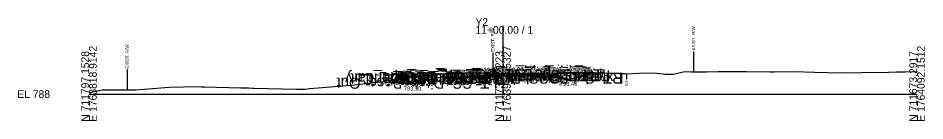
# Model space of a CAD drawing. Extents: x -26 to 1764011, y -10 to 712381.
# Drawn here: x -25.7 to 302.8, y 990.3 to 1027.5 of the extents above; entities that cross this region are included whole.
import ezdxf

# ---------------------------------------------------------------- set-up
doc = ezdxf.new("R2010")
doc.units = 0
for name, color, linetype in [('Default', 7, 'Continuous'), ('Exist Cross Section Cell', 7, 'Continuous'), ('Exist XS Center Line Elevation Label', 7, 'Continuous'), ('Exist XS Ground Line', 7, 'Continuous'), ('Old_Level_10', 7, 'Continuous'), ('Prop CMT Pvmt Course 1', 7, 'Continuous'), ('Prop CMT Pvmt Course 2', 7, 'Continuous'), ('Prop CMT Pvmt Course 3', 7, 'Continuous'), ('Prop CMT Pvmt Surface', 7, 'Continuous'), ('Prop CMT Pvmt Surface Shoulder', 7, 'Continuous'), ('Prop CMT Shld Paved Course 1', 7, 'Continuous'), ('Prop CMT Shld Paved Course 2', 7, 'Continuous'), ('Prop CMT Shld Paved Course 3', 7, 'Continuous'), ('Prop CMT Slope Grass', 7, 'Continuous'), ('Prop CMT Subgrade Earthwork', 7, 'Continuous'), ('Prop XS Ditch Standard Text', 7, 'Continuous'), ('Prop XS Earthwork Shape', 7, 'Continuous'), ('Prop XS SE Text', 7, 'Continuous'), ('Prop XS Side Slope Text', 7, 'Continuous'), ('Scratch_Level_7', 7, 'Continuous')]:
    doc.layers.add(name, color=color, linetype=linetype)

msp = doc.modelspace()

# ---------------------------------------------------------------- linework, layer by layer
at = {"layer": 'Exist Cross Section Cell'}
for p, q in [((150, 1000), (150, 1024.67)), ((0, 1000), (150, 1000)), ((150, 1000), (300, 1000))]:
    msp.add_line(p, q, dxfattribs=at)
at = {"layer": 'Exist XS Ground Line'}
msp.add_lwpolyline([(0, 1000.64), (4.88, 1001.5), (5.22, 1001.5), (14.77, 1001.52), (15.9, 1001.57), (16.96, 1001.58), (29.01, 1002.5), (39.46, 1002.81), (40.65, 1002.69), (41.81, 1002.66), (55, 1002.33), (55.44, 1002.31), (55.92, 1002.31), (57.83, 1002.23), (59.27, 1002.16), (59.86, 1002.12), (75.11, 1001.84), (77.26, 1001.81), (77.72, 1001.77), (78.16, 1001.81), (80.04, 1001.98), (96.3, 1003.37), (100.16, 1003.9), (106.64, 1004.59), (111.93, 1005.57), (116.45, 1006.01), (126.18, 1007.13), (127.43, 1007.28), (128.47, 1007.34), (138.93, 1007.78), (143.38, 1007.62), (150, 1007.48), (150.55, 1007.46), (153.6, 1007.18), (164.39, 1006.19), (170.69, 1007.55), (171.2, 1007.59), (171.75, 1007.6), (172.75, 1007.66), (173.59, 1007.67), (175.49, 1007.69), (177.79, 1007.72), (178.24, 1007.73), (178.61, 1007.73), (180.98, 1007.76), (181.97, 1007.76), (182.55, 1007.76), (182.9, 1007.76), (183.84, 1007.74), (185.22, 1007.7), (186.47, 1007.66), (188.65, 1007.63), (189.22, 1007.62), (189.9, 1007.6), (191.96, 1007.52), (192.33, 1007.5), (194.24, 1007.41), (194.75, 1007.4), (199.16, 1007.6), (204.83, 1007.74), (208.74, 1007.17), (211.75, 1007.25), (215.71, 1008.18), (218.11, 1008.08), (223.7, 1008.11), (227.97, 1008.13), (234.76, 1008.19), (238.11, 1008.21), (246.87, 1008.1), (247.83, 1008.08), (248.22, 1008.09), (255.49, 1008.22), (262.81, 1007.97), (272.66, 1007.65), (279.89, 1007.8), (289.66, 1007.98), (292.54, 1008.02), (293.2, 1008.03), (295.74, 1008.08), (300, 1008.14)], dxfattribs=at)
at = {"layer": 'Old_Level_10'}
for p, q in [((219.01, 1015.49), (219.01, 1008.09)), ((146.29, 1014.96), (146.29, 1007.55)), ((13.78, 1008.92), (13.78, 1001.52)), ((170.69, 1007.55), (170.69, 1005.5)), ((194.75, 1007.4), (194.75, 1005.35))]:
    msp.add_line(p, q, dxfattribs=at)
at = {"layer": 'Prop CMT Pvmt Course 1'}
for points in [[(134.08, 1006.42), (130.39, 1006.27)], [(130.39, 1006.27), (130.39, 1006.02)], [(130.39, 1006.02), (134.08, 1006.17)], [(150, 1007.06), (134.08, 1006.42)], [(134.08, 1006.17), (150, 1006.81)], [(150, 1007.06), (162, 1007.54)], [(162, 1007.29), (150, 1006.81)], [(150, 1006.81), (150, 1007.06)], [(162, 1007.54), (162, 1007.29)]]:
    msp.add_lwpolyline(points, dxfattribs=at)
msp.add_lwpolyline([(150, 1006.81), (150, 1006.81), (150, 1006.81), (150, 1006.81)], close=True, dxfattribs=at)
at = {"layer": 'Prop CMT Pvmt Course 2'}
for points in [[(134.08, 1006.17), (130.39, 1006.02)], [(130.39, 1005.61), (134.08, 1005.75)], [(150, 1006.81), (134.08, 1006.17)], [(134.08, 1005.75), (150, 1006.39)], [(150, 1006.81), (162, 1007.29)], [(162, 1006.87), (150, 1006.39)], [(150, 1006.47), (150, 1006.81)], [(162, 1007.29), (162, 1006.95)]]:
    msp.add_lwpolyline(points, dxfattribs=at)
at = {"layer": 'Prop CMT Pvmt Course 3'}
for points in [[(130.39, 1006.02), (130.39, 1005.61)], [(134.08, 1005.75), (130.39, 1005.61)], [(150, 1006.39), (134.08, 1005.75)], [(150, 1006.39), (162, 1006.87)], [(150, 1006.14), (150, 1006.47)], [(162, 1006.95), (162, 1006.87)]]:
    msp.add_lwpolyline(points, dxfattribs=at)
at = {"layer": 'Prop CMT Pvmt Surface'}
for points in [[(134.08, 1006.42), (130.39, 1006.27)], [(150, 1007.06), (134.08, 1006.42)], [(150, 1007.06), (162, 1007.54)]]:
    msp.add_lwpolyline(points, dxfattribs=at)
at = {"layer": 'Prop CMT Pvmt Surface Shoulder'}
for points in [[(130.39, 1006.27), (130.39, 1006.27)], [(162, 1007.54), (162, 1007.54)]]:
    msp.add_lwpolyline(points, dxfattribs=at)
at = {"layer": 'Prop CMT Shld Paved Course 1'}
for points in [[(130.39, 1006.27), (130.14, 1006.02)], [(130.14, 1006.02), (130.39, 1006.02)], [(130.39, 1006.27), (130.39, 1006.27)], [(130.39, 1006.02), (130.39, 1006.27)], [(162, 1007.54), (162, 1007.54)], [(162, 1007.54), (162.26, 1007.28)], [(162, 1007.29), (162, 1007.54)], [(162.26, 1007.28), (162, 1007.29)]]:
    msp.add_lwpolyline(points, dxfattribs=at)
at = {"layer": 'Prop CMT Shld Paved Course 2'}
for points in [[(162, 1007.29), (162.26, 1007.28), (162.68, 1006.86)], [(162, 1006.95), (162, 1007.29)], [(162.6, 1006.86), (162, 1006.87)]]:
    msp.add_lwpolyline(points, dxfattribs=at)
at = {"layer": 'Prop CMT Shld Paved Course 3'}
for points in [[(130.14, 1006.02), (129.71, 1005.59)], [(129.71, 1005.59), (130.39, 1005.61)], [(130.39, 1006.02), (130.14, 1006.02)], [(130.39, 1005.61), (130.39, 1006.02)], [(162, 1006.87), (162, 1006.95)], [(162, 1006.87), (162.6, 1006.86)], [(162.68, 1006.86), (162, 1006.87)], [(162.6, 1006.94), (162.6, 1006.94)], [(162.6, 1006.94), (162.68, 1006.86)]]:
    msp.add_lwpolyline(points, dxfattribs=at)
at = {"layer": 'Prop CMT Slope Grass'}
for points in [[(130.39, 1006.27), (126.39, 1005.95), (116.58, 1003.5), (109.85, 1005.18)], [(162, 1007.54), (166, 1007.46), (174, 1005.46), (183.19, 1007.76)]]:
    msp.add_lwpolyline(points, dxfattribs=at)
at = {"layer": 'Prop CMT Subgrade Earthwork'}
msp.add_line((129.71, 1005.59), (130.39, 1005.61), dxfattribs=at)
for points in [[(129.13, 1006.17), (129.71, 1005.59)], [(134.08, 1005.75), (130.39, 1005.61)], [(150, 1006.39), (134.08, 1005.75)], [(150, 1006.39), (162, 1006.87)], [(162, 1006.87), (162.68, 1006.86)], [(162.68, 1006.86), (170.57, 1006.31)]]:
    msp.add_lwpolyline(points, dxfattribs=at)
at = {"layer": 'Prop XS Earthwork Shape'}
for points in [[(150, 1007.06), (134.08, 1006.42), (130.39, 1006.27), (129.13, 1006.17), (126.39, 1005.95), (116.58, 1003.5), (109.85, 1005.18), (111.93, 1005.57), (116.45, 1006.01), (126.18, 1007.13), (127.43, 1007.28), (128.47, 1007.34), (138.93, 1007.78), (143.38, 1007.62), (150, 1007.48), (150.55, 1007.46), (153.46, 1007.2)], [(150, 1007.06), (134.08, 1006.42), (130.39, 1006.27), (129.13, 1006.17), (129.71, 1005.59), (130.39, 1005.61), (134.08, 1005.75), (150, 1006.39), (158.5, 1006.73), (153.6, 1007.18), (153.46, 1007.2)], [(162, 1006.87), (162.68, 1006.86), (166.32, 1006.61), (164.39, 1006.19), (158.5, 1006.73)], [(166.32, 1006.61), (167.97, 1006.96), (170.57, 1006.31)], [(170.57, 1006.31), (174, 1005.46), (183.19, 1007.76), (182.9, 1007.76), (182.55, 1007.76), (181.97, 1007.76), (180.98, 1007.76), (178.61, 1007.73), (178.24, 1007.73), (177.79, 1007.72), (175.49, 1007.69), (173.59, 1007.67), (172.75, 1007.66), (171.75, 1007.6), (171.2, 1007.59), (170.69, 1007.55), (167.97, 1006.96)]]:
    msp.add_lwpolyline(points, close=True, dxfattribs=at)

# ---------------------------------------------------------------- texts
at = {"layer": 'Default'}
msp.add_text('-', height=0.0001, dxfattribs=at).set_placement((0, 1000))
at = {"layer": 'Exist Cross Section Cell'}
for s, p in [('Y2', (140, 1024.67)), ('11+00.00 / 1', (140, 1021.87)), ('EL 788', (-26, 998.6))]:
    msp.add_text(s, height=2.8, dxfattribs=at).set_placement(p)
for s, p in [('N 711797.1528', (0, 990)), ('E 1763818.9142', (2.8, 990)), ('N 711735.2223', (150, 990)), ('E 1763955.5327', (152.8, 990)), ('N 711673.2917', (300, 990)), ('E 1764092.1512', (302.8, 990))]:
    msp.add_text(s, height=2.8, rotation=90, dxfattribs=at).set_placement(p)
at = {"layer": 'Exist XS Center Line Elevation Label'}
msp.add_text('795.48', height=1, dxfattribs=at).set_placement((147.86, 1005.48))
at = {"layer": 'Old_Level_10'}
for s, height, p in [('EXIST. R/W', 1.181, (146.88, 1015.26)), ('EXIST. R/W', 1.181, (219.61, 1015.79)), ('EXIST. R/W', 1.181, (14.37, 1009.22)), ('EOP', 0.787, (171.09, 1003.1)), ('EOP', 0.787, (195.14, 1002.95))]:
    msp.add_text(s, height=height, rotation=90, dxfattribs=at).set_placement(p)
at = {"layer": 'Prop XS Ditch Standard Text'}
for s, p in [('793.50', (114.03, 1001.27)), ('793.46', (170.58, 1002.97))]:
    msp.add_text(s, height=1.5, dxfattribs=at).set_placement(p)
at = {"layer": 'Prop XS SE Text'}
for p in [(137.48, 1007.56), (153.34, 1008.19)]:
    msp.add_text('0.040', height=1.5, rotation=2.2906, dxfattribs=at).set_placement(p)
at = {"layer": 'Prop XS Side Slope Text'}
for rotation, p in [(345.9638, (165.76, 1008.05)), (14.0362, (176.79, 1006.69)), (345.9638, (112.02, 1005.61)), (14.0362, (121.06, 1005.39))]:
    msp.add_text('4:1', height=1.5, rotation=rotation, dxfattribs=at).set_placement(p)
at = {"layer": 'Scratch_Level_7'}
for s, p in [('Exterior Boundary', (135.63, 1007.55)), ('LT_Slope_Cut', (128.92, 1007.55)), ('LT_GS_OS_CTL', (145.9, 1007.95)), ('LT_PS3_Shelf_Out', (153.87, 1007.67)), ('LT_PV1_OEOT', (147.91, 1008.27)), ('LT_PS1_OEOP', (148.18, 1008.27)), ('LT_PS3_OEOP', (148.63, 1007.67)), ('LT_PS2_OEOP', (148.94, 1008.01)), ('LT_PV2_OEOT', (148.92, 1008.02)), ('LT_PV3_OEOT', (148.95, 1007.69)), ('RT_PV1_OEEOP', (170.2, 1008.81)), ('LT_PV1_OEEOP', (169.7, 1008.81)), ('RT_PV2_OEEOP', (171.21, 1008.81)), ('RT_PV3_OEEOP', (171.24, 1008.47)), ('RT_Sub_OEEOP', (170.67, 1008.14)), ('LT_PV2_OEEOP', (170.71, 1008.81)), ('LT_PV3_OEEOP', (170.74, 1008.47)), ('LT_Sub_OEEOP', (170.17, 1008.14)), ('RT_PV1_IEEOP', (169.32, 1008.81)), ('LT_PV1_IEEOP', (168.82, 1008.81)), ('RT_PV2_IEEOP', (170.33, 1008.81)), ('LT_PV2_IEEOP', (169.82, 1008.81)), ('PV1_PGL', (160.68, 1009.06)), ('PV2_PGL', (161.68, 1008.81)), ('RT_Sub_Trench_Out', (188.88, 1008.6)), ('RT_PS3_Shelf_Out', (187.28, 1008.94)), ('RT_PV1_OEOT', (180.14, 1009.54)), ('RT_PS1_OEOP', (180.41, 1009.54)), ('RT_PV2_OEOT', (181.15, 1009.29)), ('RT_PV3_OEOT', (181.18, 1008.95)), ('RT_Sub_OEOT', (180.61, 1008.62)), ('RT_PS2_OEOP', (181.67, 1009.28)), ('RT_PS3_OEOP', (182.04, 1008.94)), ('RT_GS_OS_CTL', (186.12, 1009.22)), ('RT_Sub_OSS_DLT', (193.35, 1007.78)), ('Exterior Boundary', (193.67, 1007.78)), ('RT_Slope_Fill', (185.24, 1008.85)), ('LT_SS_Ditch_Base_Out', (148.01, 1005.95)), ('LT_Sub_OSS_DLT', (146.29, 1007.21)), ('LT_Sub_Trench_Out', (154.79, 1007.33)), ('LT_Sub_OEOT', (148.39, 1007.35))]:
    msp.add_text(s, height=4, rotation=180, dxfattribs=at).set_placement(p)

doc.saveas('drawing.dxf')
